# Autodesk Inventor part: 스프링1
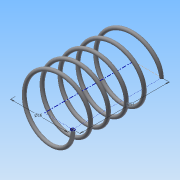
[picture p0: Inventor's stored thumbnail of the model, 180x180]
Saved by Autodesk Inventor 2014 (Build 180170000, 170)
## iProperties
Created: 2015-06
Part Number: 스프링1
Material: 강철, 연강
Document SubType Name: Modeling
Designer: Administrator
Density: 7.86 g/cm^3
Appearance: 강철
Mass: 1.53535 g
Surface Area: 7.89042 cm^2
Volume: 0.195337 cm^3
Author: Administrator
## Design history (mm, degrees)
sketch "스케치1"
  geometry: L1 (0, 0)-(8, 0); L2 (8, 0)-(8, 21.5); L3 (8, 21.5)-(0, 21.5); L4 (0, 21.5)-(0, 0); C1 r 0.5 at (8, 0)
  constraints: 8 end point, 2 parallel, 1 centre point, 1 coincident, 1 horizontal, 1 perpendicular
  dimensions: "d1" = 1 diameter of C1; "d2" = 16 diameter of L2 L4; "d3" = 21.5 distance of L1.end L2.end (derived)
feature "코일1" sketch "스케치1" pitch "d4" = 10; turns "d6" = 5; dims "d5" = 21.5 (= d3), "d7" = 0, angle "d8" = 90 deg, angle "d9" = 90 deg, "d10" = 0, "d11" = 0
sketch "스케치2"
  geometry: L1 (-8.5, 0)-(-7.5, 0) reference; 1 further point
  constraints: 1 horizontal alignment
extrude "돌출1" cut sketch "스케치2" stored distance "d12" = 10; taper "d13" = 0 deg
node "작업 평면1"
sketch "스케치3"
  geometry: L1 (8.5, 0)-(7.5, 0) reference; 1 further point
  constraints: 1 horizontal alignment
extrude "돌출2" cut sketch "스케치3" stored distance "d15" = 10; taper "d16" = 0 deg
node "솔리드1"
node "절단 모서리 투영1"
node "절단 모서리 투영2"
other parameters: "d14" = -21.5 (= -d3)
